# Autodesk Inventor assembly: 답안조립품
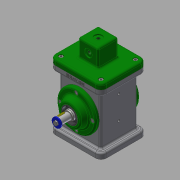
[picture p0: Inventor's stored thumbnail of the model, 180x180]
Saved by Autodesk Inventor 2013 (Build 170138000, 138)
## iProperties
Created: 2017-08
Part Number: 답안조립품
Document SubType Name: Assembly
Designer: Administrator
Author: Administrator
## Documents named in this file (18)
- C:\Users\Administrator\Desktop\470807V1020\답안조립품.iam
- C:\Users\Administrator\Desktop\470807V1020\본체.ipt
- C:\Users\Administrator\Desktop\470807V1020\470807V1020\E-링.ipt
- C:\Users\Administrator\Desktop\470807V1020\470807V1020\V-벨트풀리.ipt
- C:\Users\Administrator\Desktop\470807V1020\470807V1020\덮개.ipt
- C:\Users\Administrator\Desktop\470807V1020\470807V1020\뒤커버.ipt
- C:\Users\Administrator\Desktop\470807V1020\470807V1020\링크.ipt
- C:\Users\Administrator\Desktop\470807V1020\470807V1020\베어링 17 x 40 x 12.ipt
- C:\Users\Administrator\Desktop\470807V1020\470807V1020\볼트 M4 x 8.ipt
- C:\Users\Administrator\Desktop\470807V1020\470807V1020\볼트 M4 x 10.ipt
- C:\Users\Administrator\Desktop\470807V1020\470807V1020\슬라이더.ipt
- C:\Users\Administrator\Desktop\470807V1020\470807V1020\앞커버.ipt
- C:\Users\Administrator\Desktop\470807V1020\470807V1020\오일 실 17 30 8.ipt
- C:\Users\Administrator\Desktop\470807V1020\470807V1020\와셔 4x16.ipt
- C:\Users\Administrator\Desktop\470807V1020\470807V1020\클레비스 핀 6 x 22.ipt
- 클레비스 핀 6 x 22.ipt
- C:\Users\Administrator\Desktop\470807V1020\470807V1020\키 4 x 4 x 12.ipt
- C:\Users\Administrator\Desktop\470807V1020\470807V1020\편심축.ipt
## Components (2 placed, 2 different names)
1. E-링:1
2. V-벨트풀리:1
